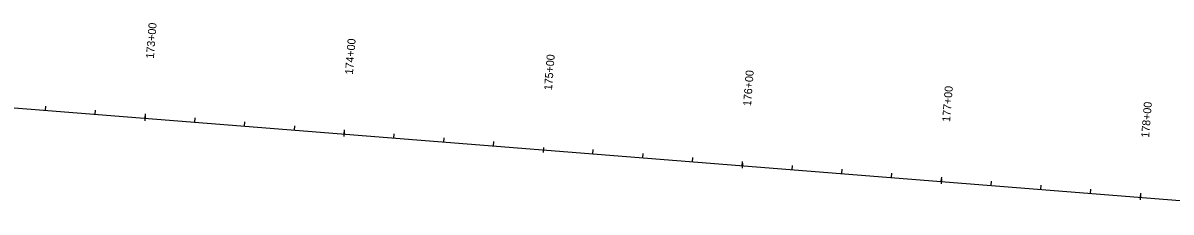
# Model space of a CAD drawing. Extents: x 20500393 to 20505339, y 7953466 to 7954298.
# Drawn here: x 20500950 to 20501525, y 7953909 to 7954004 of the extents above; entities that cross this region are included whole.
import ezdxf

# ---------------------------------------------------------------- set-up
doc = ezdxf.new("R2010")
doc.units = 0
for name, color, linetype in [('_CIVIL_CONSTRUCTION', 7, 'Continuous'), ('TextAlignmentLrg', 7, 'Continuous'), ('TextAlignmentSml', 7, 'Continuous')]:
    doc.layers.add(name, color=color, linetype=linetype)

msp = doc.modelspace()

# ---------------------------------------------------------------- linework, layer by layer
at = {"layer": '_CIVIL_CONSTRUCTION'}
msp.add_line((20500850.16, 7953968.94), (20501601.96, 7953909.2), dxfattribs=at)
msp.add_line((20500850.16, 7953968.94), (20501601.96, 7953909.2), dxfattribs=at)
at = {"layer": 'TextAlignmentLrg'}
for p, q in [((20501011.07, 7953956.16), (20501011.24, 7953958.33)), ((20501110.76, 7953948.24), (20501110.93, 7953950.41)), ((20501210.54, 7953941.53), (20501210.35, 7953939.09)), ((20501310.13, 7953932.39), (20501310.3, 7953934.57)), ((20501409.81, 7953924.47), (20501409.99, 7953926.65)), ((20501509.5, 7953916.55), (20501509.67, 7953918.73))]:
    msp.add_line(p, q, dxfattribs=at)
at = {"layer": 'TextAlignmentSml'}
for p, q in [((20500961.23, 7953960.12), (20500961.4, 7953962.3)), ((20500986.15, 7953958.14), (20500986.32, 7953960.31)), ((20501011.17, 7953957.38), (20501010.97, 7953954.94)), ((20501035.99, 7953954.18), (20501036.17, 7953956.35)), ((20501060.91, 7953952.2), (20501061.09, 7953954.37)), ((20501085.84, 7953950.22), (20501086.01, 7953952.39)), ((20501110.85, 7953949.46), (20501110.66, 7953947.02)), ((20501135.68, 7953946.26), (20501135.85, 7953948.43)), ((20501160.6, 7953944.27), (20501160.77, 7953946.45)), ((20501185.52, 7953942.29), (20501185.69, 7953944.47)), ((20501210.54, 7953941.53), (20501210.35, 7953939.09)), ((20501235.36, 7953938.33), (20501235.54, 7953940.51)), ((20501260.29, 7953936.35), (20501260.46, 7953938.53)), ((20501285.21, 7953934.37), (20501285.38, 7953936.55)), ((20501310.23, 7953933.61), (20501310.03, 7953931.17)), ((20501335.05, 7953930.41), (20501335.22, 7953932.59)), ((20501359.97, 7953928.43), (20501360.14, 7953930.61)), ((20501384.89, 7953926.45), (20501385.07, 7953928.63)), ((20501409.91, 7953925.69), (20501409.72, 7953923.25)), ((20501434.74, 7953922.49), (20501434.91, 7953924.67)), ((20501459.66, 7953920.51), (20501459.83, 7953922.69)), ((20501484.58, 7953918.53), (20501484.75, 7953920.71)), ((20501509.6, 7953917.77), (20501509.4, 7953915.33))]:
    msp.add_line(p, q, dxfattribs=at)

# ---------------------------------------------------------------- texts
at = {"layer": 'TextAlignmentLrg'}
msp.add_text('175+00', height=4.008, rotation=85.45642, dxfattribs=at).set_placement((20501214.82, 7953970.06))
at = {"layer": 'TextAlignmentSml'}
for s, p in [('173+00', (20501015.45, 7953985.9)), ('174+00', (20501115.13, 7953977.98)), ('175+00', (20501214.82, 7953970.06)), ('176+00', (20501314.5, 7953962.14)), ('177+00', (20501414.19, 7953954.22)), ('178+00', (20501513.87, 7953946.3))]:
    msp.add_text(s, height=4.008, rotation=85.45642, dxfattribs=at).set_placement(p)

doc.saveas('drawing.dxf')
